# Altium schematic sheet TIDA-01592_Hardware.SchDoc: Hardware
size 431 x 279 mm; Date: Not shown in title block; ApprovedBy: Not shown in title block; CheckedBy: Not shown in title block; Author: Not shown in title block; CompanyName: Not shown in title block; DrawnBy: Abhishek Vishwa; Engineer: Abhishek Vishwa; Organization: Not shown in title block; Address1: Not shown in title block; Address2: Not shown in title block; Address3: Not shown in title block; Address4: Not shown in title block; DocumentNumber: 1; Revision: Use project parameter SCH_Rev; SheetNumber: 5; SheetTotal: 5; PageSetup: Record=PageOptions¦CenterHorizontal=True¦CenterVertical=True¦PrintScale=1.00¦XCorrection=1.00¦YCorrection=1.00¦PrintKind=0¦BorderSize=5000000¦LeftOffset=0¦BottomOffset=0¦Orientation=2¦PaperLength=1000¦PaperWidth=1000¦Scale=100¦PaperSource=15¦PrintQuality=600¦MediaType=1¦DitherType=10¦PaperKind=Letter¦PrintScaleMode=1
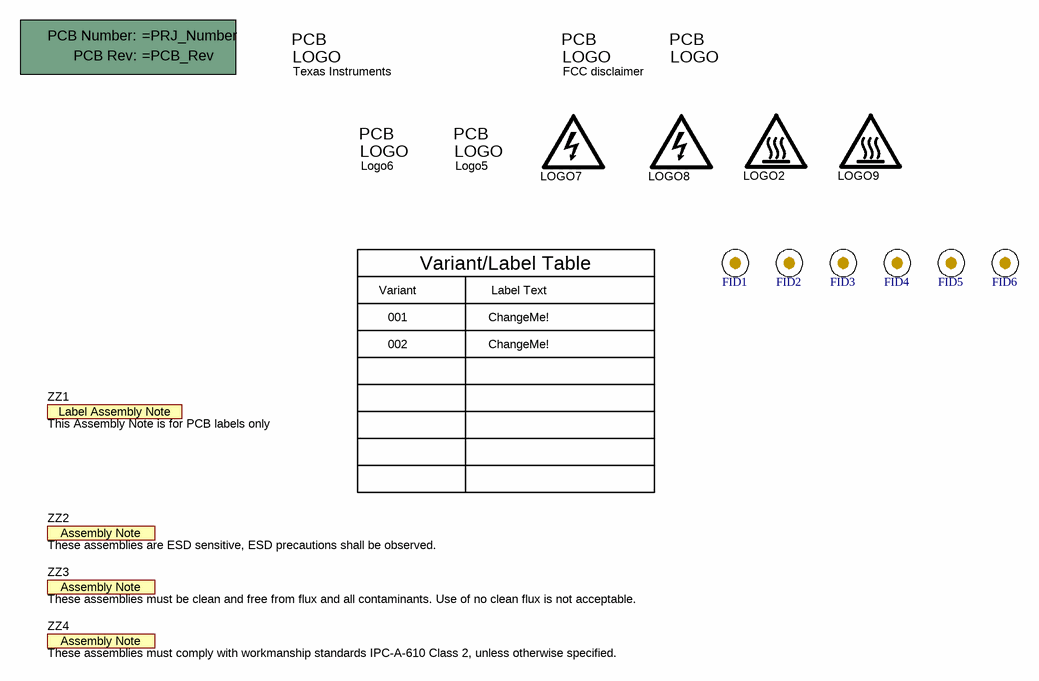
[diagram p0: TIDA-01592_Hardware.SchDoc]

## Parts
!PCB1  Printed Circuit Board  (value not drawn)  (mechanical)
FID1  Fiducial  [Fiducial10-30]  (value not drawn)
FID2  Fiducial  [Fiducial10-30]  (value not drawn)
FID3  Fiducial  [Fiducial10-30]  (value not drawn)
FID4  Fiducial  [Fiducial10-30]  (value not drawn)
FID5  Fiducial  [Fiducial10-30]  (value not drawn)
FID6  Fiducial  [Fiducial10-30]  (value not drawn)
Logo1  Texas Instruments  [TI_Symbol_Overlay_Small]  (no BOM)
LOGO2  CAUTION HOT SURFACE  [IEC_HotSurface_Small]  (value not drawn)  (no BOM)
Logo3  FCC disclaimer  [FCC_disclaimer]  (no BOM)
Logo4  ESD Susceptible  [ESD_Overlay_Small]  (value not drawn)  (no BOM)
Logo5  CAUTION.  READ USER GUIDE BEFORE USE  [IEC_Caution_Small]  (value not drawn)  (no BOM)
Logo6  CAUTION.  READ USER GUIDE BEFORE USE  [IEC_Caution_Small]  (value not drawn)  (no BOM)
LOGO7  DANGER HIGH VOLTAGE  [IEC_HighVoltage_Small]  (value not drawn)  (no BOM)
LOGO8  DANGER HIGH VOLTAGE  [IEC_HighVoltage_Small]  (value not drawn)  (no BOM)
LOGO9  CAUTION HOT SURFACE  [IEC_HotSurface_Small]  (value not drawn)  (no BOM)
ZZ1  This Assembly Note is for PCB labels only  [AssemblyNoteLabel]  (no BOM)
ZZ2  These assemblies are ESD sensitive, ESD precautions shall be observed.  [AssemblyNote]  (no BOM)
ZZ3  These assemblies must be clean and free from flux and all contaminants. Use of no clean flux is not acceptable.  [AssemblyNote]  (no BOM)
ZZ4  These assemblies must comply with workmanship standards IPC-A-610 Class 2, unless otherwise specified.  [AssemblyNote]  (no BOM)

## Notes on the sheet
- Variant
- Variant/Label Table
- Label Text
- 001
- 002
- ChangeMe!

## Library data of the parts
!PCB1 = PCB: Manufacturer: Any; SymbolCreator: a0412235
FID1-FID6 = Fiducial: Fiducial mark.  There is nothing to buy or mount.; SymbolCreator: codlsc
Logo1 = TI_Logo: Texas Instrument Corporate Signature; SymbolCreator: codlsc
LOGO2 LOGO9 = IEC_HotSurface: IEC 61010-1 Hot Surface Warning; SymbolCreator: a0412235
Logo3 = FCC_disclaimer: SymbolCreator: codlsc
Logo4 = ESD_Susceptible: ESD Susceptible Symbol; SymbolCreator: a0412235
Logo5 Logo6 = IEC_Caution: IEC 61010-1 Caution Warning; SymbolCreator: a0412235
LOGO7 LOGO8 = IEC_HighVoltage: IEC 61010-1 High Voltage Warning; SymbolCreator: a0412235
ZZ1 = AssemblyNoteLabel: SymbolCreator: a0412235
ZZ2-ZZ4 = AssemblyNote: SymbolCreator: codlsc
